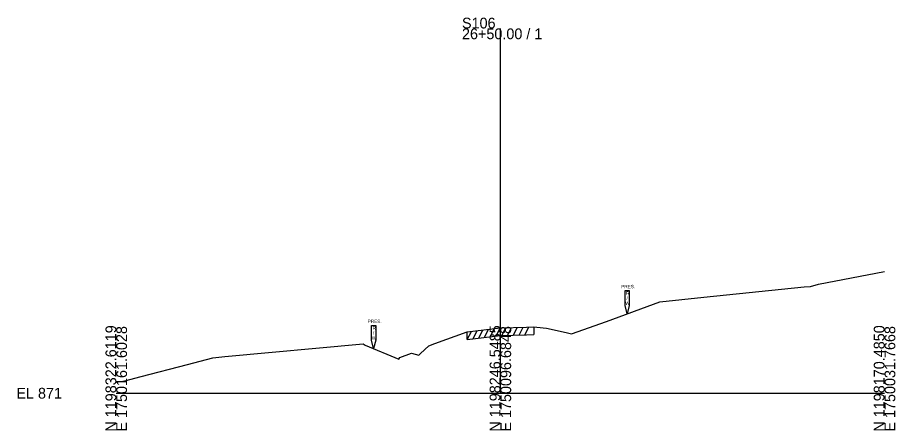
# Model space of a CAD drawing. Extents: x -26 to 1203, y -10 to 19527.
# Drawn here: x -25.7 to 202.8, y 2990.3 to 3097.8 of the extents above; entities that cross this region are included whole.
import ezdxf

# ---------------------------------------------------------------- set-up
doc = ezdxf.new("R2010")
doc.units = 0
for name, color, linetype in [('RD_GPK_XS_Cell', 7, 'Continuous'), ('RD_XS_ExGround', 7, 'Continuous'), ('RD_XS_ExPaveRet', 7, 'Continuous'), ('RD_XS_ExRW', 7, 'Continuous'), ('RD_XS_TX_Elev_EX', 7, 'Continuous')]:
    doc.layers.add(name, color=color, linetype=linetype)

msp = doc.modelspace()

# ---------------------------------------------------------------- linework, layer by layer
at = {"layer": 'RD_GPK_XS_Cell'}
for p, q in [((100, 3000), (100, 3094.98)), ((0, 3000), (100, 3000)), ((100, 3000), (200, 3000))]:
    msp.add_line(p, q, dxfattribs=at)
at = {"layer": 'RD_XS_ExGround'}
msp.add_lwpolyline([(0, 3002.89), (2.24, 3003.22), (6.47, 3004.33), (18.56, 3007.47), (25.14, 3009.21), (28.24, 3009.57), (64.26, 3012.87), (64.8, 3012.54), (73.56, 3008.89), (73.86, 3009.32), (76.86, 3010.46), (78.75, 3009.93), (79.22, 3010.35), (81.38, 3012.38), (82.96, 3012.94), (91.38, 3015.97), (97.83, 3016.77), (99.95, 3017.01), (106.78, 3017.21), (108.71, 3017.26), (109.47, 3017.2), (111.98, 3016.92), (117.14, 3015.77), (118.54, 3015.46), (127.59, 3018.71), (141.49, 3023.81), (152.94, 3025.05), (179.08, 3027.68), (180.71, 3027.8), (182.83, 3028.43), (200, 3031.66)], dxfattribs=at)
at = {"layer": 'RD_XS_ExPaveRet'}
for p, q in [((95.88, 3014.53), (96.94, 3016.66)), ((97.38, 3014.72), (98.44, 3016.84)), ((98.88, 3014.89), (99.94, 3017.01)), ((100.38, 3015.03), (101.39, 3017.05)), ((101.88, 3015.07), (102.89, 3017.1)), ((103.38, 3015.11), (104.39, 3017.14)), ((104.88, 3015.15), (105.89, 3017.18)), ((106.38, 3015.19), (107.39, 3017.22)), ((108.71, 3017.26), (108.71, 3015.26)), ((91.38, 3013.97), (92.44, 3016.11)), ((91.38, 3013.97), (91.38, 3015.97)), ((91.38, 3013.97), (97.83, 3014.77)), ((92.88, 3014.16), (93.94, 3016.29)), ((94.38, 3014.35), (95.44, 3016.48)), ((97.83, 3014.77), (99.95, 3015.01)), ((99.95, 3015.01), (106.78, 3015.21)), ((106.78, 3015.21), (108.71, 3015.26))]:
    msp.add_line(p, q, dxfattribs=at)
at = {"layer": 'RD_XS_ExRW'}
for points in [[(132.45, 3026.71), (133.55, 3026.71), (133.55, 3022.88), (133, 3020.7), (132.45, 3022.88)], [(66.45, 3017.64), (67.55, 3017.64), (67.55, 3013.81), (67, 3011.62), (66.45, 3013.81)]]:
    msp.add_lwpolyline(points, close=True, dxfattribs=at)

# ---------------------------------------------------------------- texts
at = {"layer": 'RD_GPK_XS_Cell'}
for s, p in [('S106', (90, 3094.98)), ('26+50.00 / 1', (90, 3092.18)), ('EL 871', (-26, 2998.6))]:
    msp.add_text(s, height=2.8, dxfattribs=at).set_placement(p)
for s, p in [('N 1198322.6119', (0, 2990)), ('E 1750161.6028', (2.8, 2990)), ('N 1198246.5485', (100, 2990)), ('E 1750096.6848', (102.8, 2990)), ('N 1198170.4850', (200, 2990)), ('E 1750031.7668', (202.8, 2990))]:
    msp.add_text(s, height=2.8, rotation=90, dxfattribs=at).set_placement(p)
at = {"layer": 'RD_XS_ExRW'}
for s, p in [('PRES.', (131.45, 3027.34)), ('R', (132.71, 3025.62)), ('W', (132.53, 3023)), ('/', (132.83, 3024.31)), ('PRES.', (65.45, 3018.26)), ('R', (66.71, 3016.54)), ('W', (66.53, 3013.92)), ('/', (66.83, 3015.23))]:
    msp.add_text(s, height=0.875, dxfattribs=at).set_placement(p)
at = {"layer": 'RD_XS_TX_Elev_EX'}
msp.add_text('879.51', height=0.0975, rotation=90, dxfattribs=at).set_placement((100.1, 3017.02))

doc.saveas('drawing.dxf')
